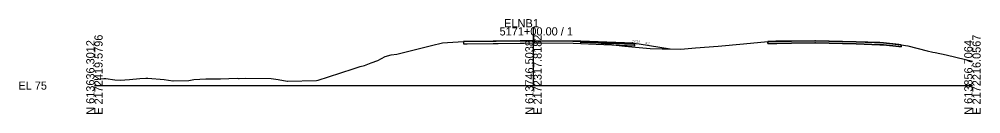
# Model space of a CAD drawing. Extents: x -26 to 1303, y -3010 to 12038.
# Drawn here: x -25.7 to 302.8, y -509.7 to -477.2 of the extents above; entities that cross this region are included whole.
import ezdxf

# ---------------------------------------------------------------- set-up
doc = ezdxf.new("R2010")
doc.units = 0
for name, color, linetype in [('RD_GPK_XS_Cell', 7, 'Continuous'), ('RD_XS_Base', 7, 'Continuous'), ('RD_XS_ExGround', 7, 'Continuous'), ('RD_XS_ExPaveRet', 7, 'Continuous'), ('RD_XS_Greenside', 7, 'Continuous'), ('RD_XS_Pave', 7, 'Continuous'), ('RD_XS_PaveOvlay_CP', 7, 'Continuous'), ('RD_XS_TieSlope', 7, 'Continuous'), ('RD_XS_TX_ShdSlope', 7, 'Continuous'), ('RD_XS_TX_Slope', 7, 'Continuous')]:
    doc.layers.add(name, color=color, linetype=linetype)

msp = doc.modelspace()

# ---------------------------------------------------------------- linework, layer by layer
at = {"layer": 'RD_GPK_XS_Cell'}
for p, q in [((150, -500), (150, -480)), ((0, -500), (150, -500)), ((150, -500), (300, -500))]:
    msp.add_line(p, q, dxfattribs=at)
at = {"layer": 'RD_XS_Base'}
for p, q in [((184.11, -485.79), (166.15, -485.07)), ((166.15, -485.5), (166.15, -485.57)), ((166.15, -485.57), (184.61, -486.31)), ((184.61, -485.81), (184.11, -485.79)), ((184.11, -485.79), (184.11, -485.79)), ((184.61, -486.31), (184.61, -485.81)), ((184.61, -485.81), (184.61, -485.81))]:
    msp.add_line(p, q, dxfattribs=at)
at = {"layer": 'RD_XS_ExGround'}
msp.add_lwpolyline([(0, -497.87), (0.13, -497.87), (3.23, -497.51), (3.95, -497.54), (6.93, -498.04), (8.85, -498.09), (12, -497.86), (15.46, -497.53), (17.58, -497.41), (17.76, -497.41), (18.25, -497.47), (23.81, -497.92), (26.79, -498.34), (26.83, -498.34), (26.88, -498.34), (32.22, -498.3), (34.01, -497.86), (38.02, -497.69), (42.35, -497.63), (43.1, -497.65), (48.82, -497.5), (49.22, -497.51), (49.29, -497.51), (49.44, -497.51), (51.58, -497.5), (60.4, -497.53), (62.75, -497.92), (65.84, -498.49), (65.99, -498.48), (75.93, -498.26), (76.39, -498.19), (80.02, -496.96), (88.35, -494.22), (90.78, -493.44), (92.32, -493.06), (94.58, -492.24), (96.8, -491.42), (99.29, -490.07), (101.38, -489.5), (103.3, -489.16), (115.14, -486.29), (118.91, -485.36), (120.69, -485.25), (126.14, -484.91), (126.17, -484.91), (137.23, -484.79), (145.45, -484.66), (150.51, -484.59), (163.45, -484.72), (166.16, -484.75), (168.31, -484.95), (174.37, -485.5), (178.23, -486.07), (181.26, -486.49), (183.64, -486.7), (189.93, -487.23), (194.01, -487.33), (195.87, -487.37), (200.33, -487.46), (205.37, -487.07), (213.08, -486.5), (221.72, -485.65), (230.09, -484.84), (237.87, -484.73), (238.14, -484.73), (246.26, -484.61), (260.26, -484.93), (269.58, -485.29), (275.65, -485.98), (277.91, -486.41), (284.54, -488.05), (286.49, -488.5), (287.27, -488.68), (290.97, -489.5), (297.65, -491.08), (299.52, -491.5), (300, -491.58)], dxfattribs=at)
at = {"layer": 'RD_XS_ExPaveRet'}
for points in [[(166.16, -484.75), (166.16, -484.75), (166.15, -484.75), (163.58, -484.72), (150.53, -484.59), (150.51, -484.59), (150.48, -484.59), (150.42, -484.59), (146.82, -484.64), (145.45, -484.66), (137.98, -484.77), (137.23, -484.79), (136.22, -484.8), (127.37, -484.89), (126.5, -484.9), (126.14, -484.91), (126.14, -484.91), (126.14, -485.03), (126.14, -485.66), (126.14, -485.66), (126.5, -485.65), (127.37, -485.64), (136.22, -485.55), (137.23, -485.54), (137.98, -485.52), (145.45, -485.41), (146.82, -485.39), (150.42, -485.34), (150.48, -485.34), (150.51, -485.34), (150.53, -485.34), (163.58, -485.47), (166.15, -485.5), (166.16, -485.5), (166.16, -485.5), (166.16, -485.5), (166.16, -485.5), (166.16, -485.38), (166.16, -484.75), (166.16, -484.75), (166.16, -484.75)], [(166.16, -484.75), (166.15, -484.75), (163.58, -484.72), (150.53, -484.59), (150.51, -484.59), (150.48, -484.59), (150.42, -484.59), (146.82, -484.64), (145.45, -484.66), (137.98, -484.77), (137.23, -484.79), (136.22, -484.8), (127.37, -484.89), (126.5, -484.9), (126.14, -484.91), (126.14, -485.03), (126.14, -485.66), (126.5, -485.65), (127.37, -485.64), (136.22, -485.55), (137.23, -485.54), (137.98, -485.52), (145.45, -485.41), (146.82, -485.39), (150.42, -485.34), (150.48, -485.34), (150.51, -485.34), (150.53, -485.34), (163.58, -485.47), (166.15, -485.5), (166.16, -485.5), (166.16, -485.5), (166.16, -485.38), (166.16, -484.75), (166.16, -484.75)], [(275.65, -485.98), (275.65, -485.98), (275.65, -486.22), (275.65, -486.73), (275.65, -486.73), (275.65, -486.73), (275.64, -486.73), (274.8, -486.64), (269.58, -486.04), (268.36, -485.99), (260.26, -485.68), (246.41, -485.37), (246.26, -485.36), (246.17, -485.36), (246.17, -485.36), (238.13, -485.48), (233.14, -485.55), (232.87, -485.55), (230.09, -485.59), (230.09, -485.59), (230.09, -485.59), (230.09, -485.36), (230.09, -484.84), (230.09, -484.84), (230.09, -484.84), (232.87, -484.8), (233.14, -484.8), (238.13, -484.73), (246.17, -484.61), (246.17, -484.61), (246.26, -484.61), (246.41, -484.62), (260.26, -484.93), (268.36, -485.24), (269.58, -485.29), (274.8, -485.89), (275.64, -485.98), (275.65, -485.98), (275.65, -485.98)], [(275.65, -485.98), (275.64, -485.98), (274.8, -485.89), (269.58, -485.29), (268.36, -485.24), (260.26, -484.93), (246.41, -484.62), (246.26, -484.61), (246.17, -484.61), (246.17, -484.61), (238.13, -484.73), (233.14, -484.8), (232.87, -484.8), (230.09, -484.84), (230.09, -484.84), (230.09, -485.36), (230.09, -485.59), (230.09, -485.59), (232.87, -485.55), (233.14, -485.55), (238.13, -485.48), (246.17, -485.36), (246.17, -485.36), (246.26, -485.36), (246.41, -485.37), (260.26, -485.68), (268.36, -485.99), (269.58, -486.04), (274.8, -486.64), (275.64, -486.73), (275.65, -486.73), (275.65, -486.73), (275.65, -486.22), (275.65, -485.98), (275.65, -485.98)]]:
    msp.add_lwpolyline(points, dxfattribs=at)
at = {"layer": 'RD_XS_Greenside'}
msp.add_line((186.11, -485.63), (196.67, -487.39), dxfattribs=at)
at = {"layer": 'RD_XS_Pave'}
for p, q in [((184.11, -485.47), (166.15, -484.75)), ((184.11, -485.63), (166.15, -484.91)), ((166.15, -484.91), (184.11, -485.63)), ((166.15, -485.07), (184.11, -485.79)), ((184.11, -485.63), (184.11, -485.47)), ((184.11, -485.47), (184.11, -485.47)), ((184.11, -485.79), (184.11, -485.63)), ((184.11, -485.63), (184.11, -485.63))]:
    msp.add_line(p, q, dxfattribs=at)
at = {"layer": 'RD_XS_PaveOvlay_CP'}
msp.add_line((184.11, -485.47), (166.15, -484.75), dxfattribs=at)
at = {"layer": 'RD_XS_TieSlope'}
msp.add_line((184.11, -485.47), (186.11, -485.63), dxfattribs=at)

# ---------------------------------------------------------------- texts
at = {"layer": 'RD_GPK_XS_Cell'}
for s, p in [('ELNB1', (140, -480)), ('5171+00.00 / 1', (138.42, -482.8)), ('EL 75', (-26, -501.4))]:
    msp.add_text(s, height=2.8, dxfattribs=at).set_placement(p)
for s, p in [('E 2172419.5796', (2.8, -510)), ('E 2172317.8182', (152.8, -510)), ('E 2172216.0567', (302.8, -510)), ('N 613636.3012', (0, -510)), ('N 613746.5038', (150, -510)), ('N 613856.7064', (300, -510))]:
    msp.add_text(s, height=2.8, rotation=90, dxfattribs=at).set_placement(p)
at = {"layer": 'RD_XS_TX_ShdSlope'}
msp.add_text('12.5:1', height=0.75, rotation=355.4261, dxfattribs=at).set_placement((183.69, -485.1))
at = {"layer": 'RD_XS_TX_Slope'}
msp.add_text('6:1', height=0.75, rotation=350.5377, dxfattribs=at).set_placement((188.27, -485.68))

doc.saveas('drawing.dxf')
